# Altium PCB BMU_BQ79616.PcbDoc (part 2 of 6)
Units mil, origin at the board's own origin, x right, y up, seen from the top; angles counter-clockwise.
Board outline 7605 x 4005 mil, 4 copper layers (Top Layer, Layer 1, Layer 2, Bottom Layer), stack 37.446 mil thick; 709 components, 447 nets, 2028 pads, 1862 vias.
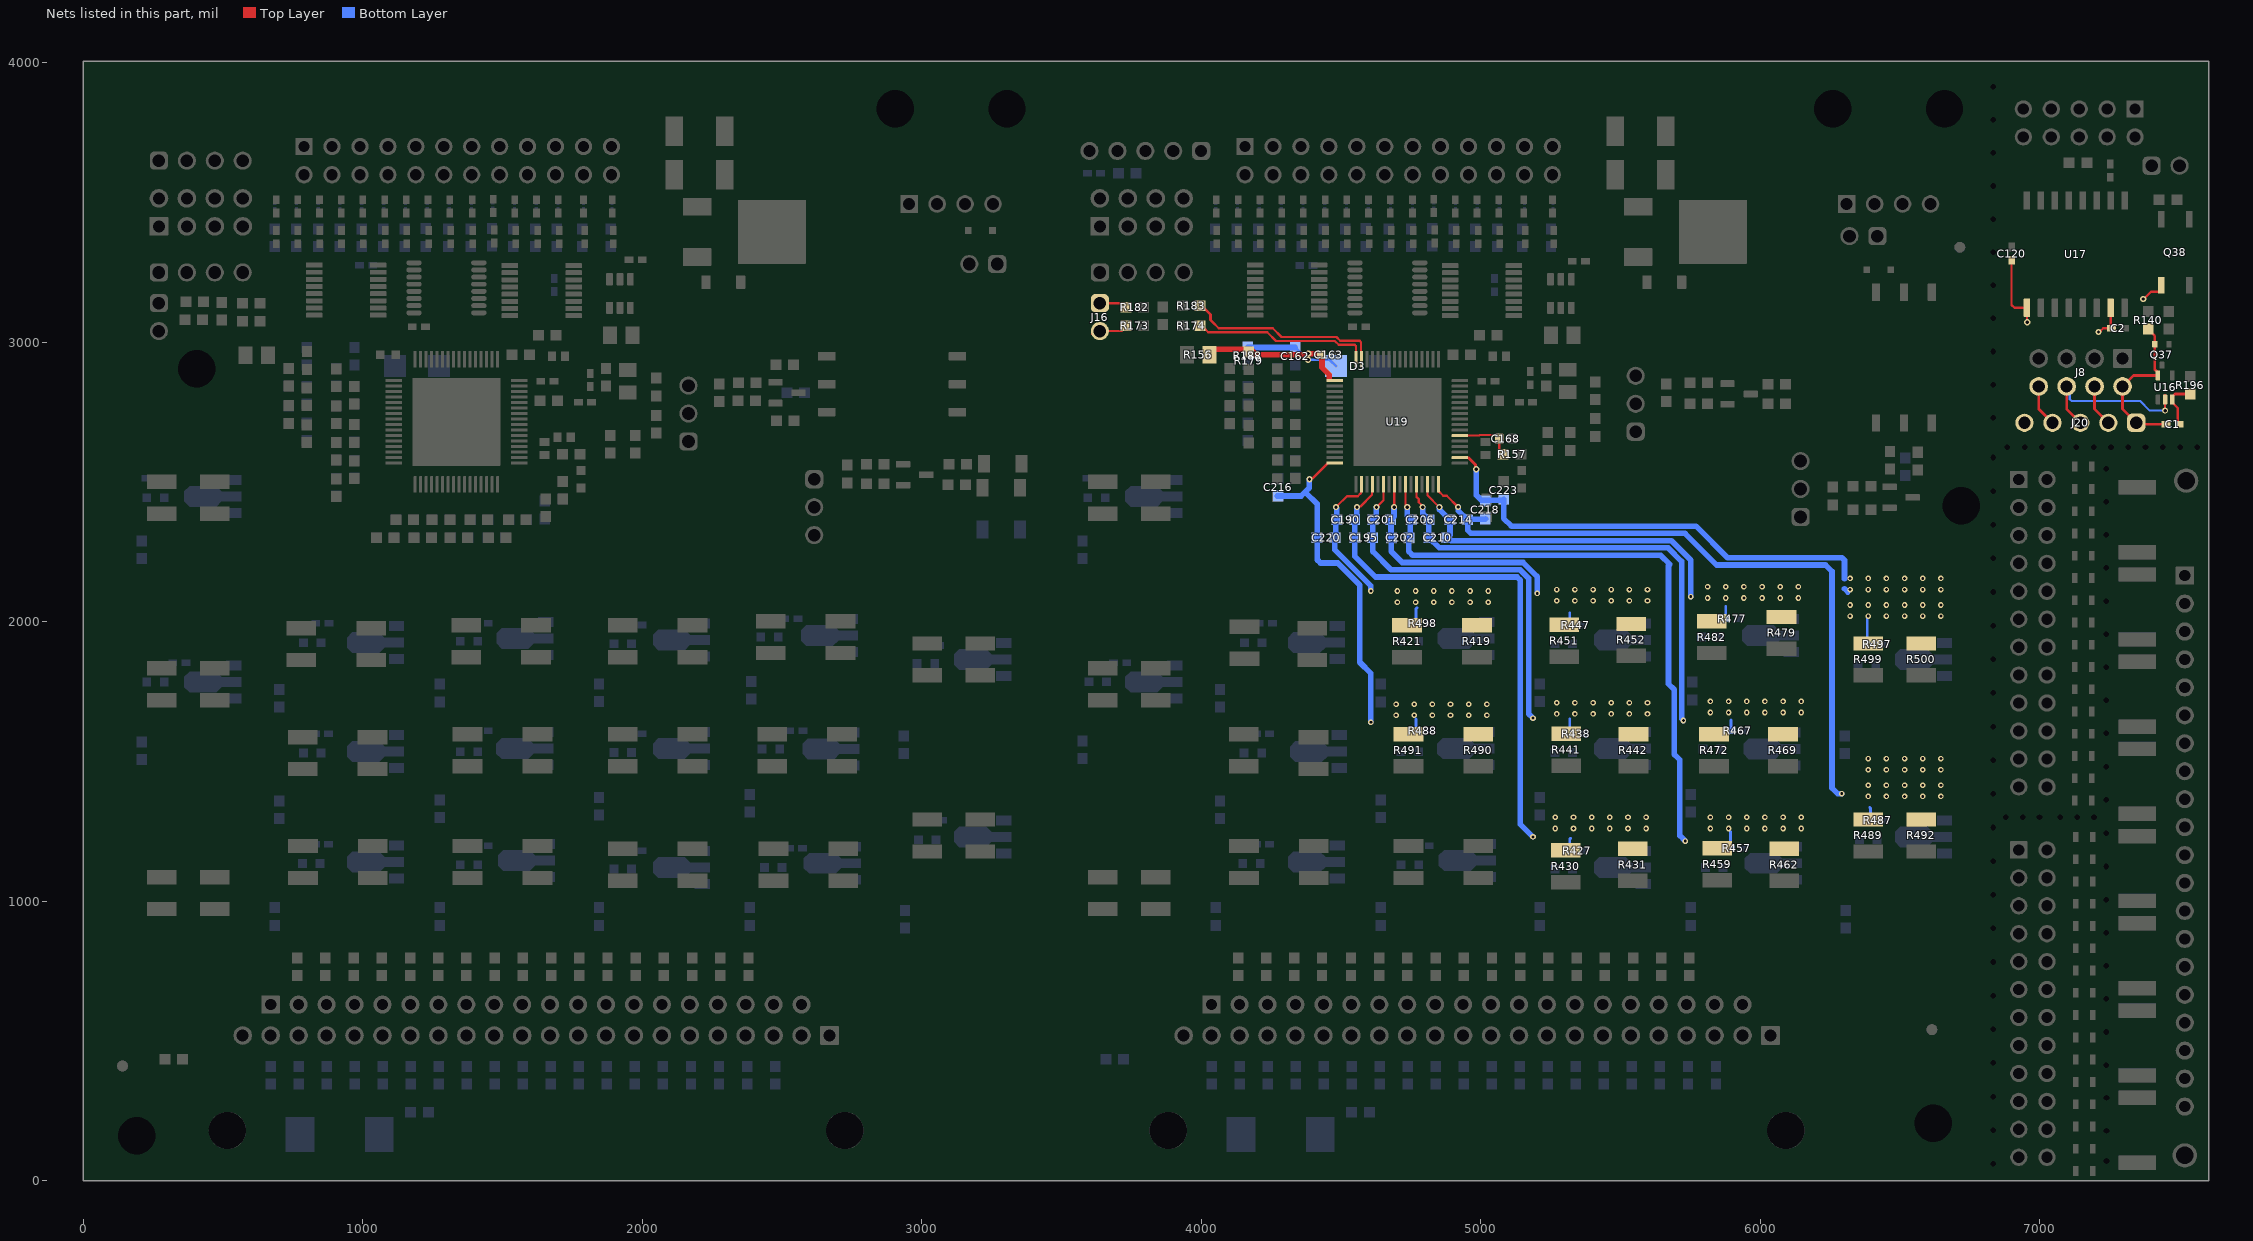
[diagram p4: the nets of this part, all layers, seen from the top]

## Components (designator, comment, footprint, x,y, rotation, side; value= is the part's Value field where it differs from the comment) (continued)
R432 "RC1210FR-0730RL" 1210 3647.36,1776.25 r90 top value=30.0
R433 "ERA-3AEB101V" 0603 5040.8,765 r90 top value=100
R434 "ERA-3AEB101V" 0603 4232.36,765 r90 top value=100
R435 "CRCW06031K00JNEA" 0603 5212.36,1340 r90 bottom value=1.0k
R436 "CRCW06031K00JNEA" 0603 3575.31,2257.26 r90 bottom value=1.0k
R437 "CRCW0402300RJNED" 0402 3615.31,2513.75 r0 bottom value=300
R438 "CRCW0402300RJNED" 0402 5342.36,1598.77 r0 bottom value=300
R439 "RC1210FR-0730RL" 1210 3647.36,2443.75 r90 top value=30.0
R440 "RC1210FR-0730RL" 1210 3837.36,2443.75 r90 top value=30.0
R441 "RC1210FR-0730RL" 1210 5306.93,1542.09 r90 top value=30.0
R442 "RC1210FR-0730RL" 1210 5546.93,1540 r90 top value=30.0
R443 "ERA-3AEB101V" 0603 5141.74,765 r90 top value=100
R444 "ERA-3AEB101V" 0603 4332.36,765 r90 top value=100
R445 "CRCW06031K00JNEA" 0603 5212.36,1746.5 r90 bottom value=1.0k
R446 "CRCW06031K00JNEA" 0603 4052.36,945 r90 bottom value=1.0k
R447 "CRCW0402300RJNED" 0402 5340.39,1988.15 r0 bottom value=300
R448 "CRCW0402300RJNED" 0402 4221.14,1203.76 r0 bottom value=300
R449 "RC1210FR-0730RL" 1210 4152.85,1140 r90 top value=30.0
R450 "RC1210FR-0730RL" 1210 4402.96,1140 r90 top value=30.0
R451 "RC1210FR-0730RL" 1210 5299.57,1932.09 r90 top value=30.0
R452 "RC1210FR-0730RL" 1210 5539.57,1935 r90 top value=30.0
R453 "ERA-3AEB101V" 0603 5242.67,765 r90 top value=100
R454 "ERA-3AEB101V" 0603 4432.36,765 r90 top value=100
R455 "CRCW06031K00JNEA" 0603 5752.36,945 r90 bottom value=1.0k
R456 "CRCW06031K00JNEA" 0603 4067.36,1326.5 r90 bottom value=1.0k
R457 "CRCW0402300RJNED" 0402 5917.36,1190 r0 bottom value=300
R458 "CRCW0402300RJNED" 0402 4221.14,1598.76 r0 bottom value=300
R459 "RC1210FR-0730RL" 1210 5846.93,1132.09 r90 top value=30.0
R460 "RC1210FR-0730RL" 1210 4151.82,1539.84 r90 top value=30.0
R461 "RC1210FR-0730RL" 1210 4401.93,1530 r90 top value=30.0
R462 "RC1210FR-0730RL" 1210 6086.93,1130 r90 top value=30.0
R463 "ERA-3AEB101V" 0603 5343.61,765 r90 top value=100
R464 "ERA-3AEB101V" 0603 4536.11,765 r90 top value=100
R465 "CRCW06031K00JNEA" 0603 5752.36,1350 r90 bottom value=1.0k
R466 "CRCW06031K00JNEA" 0603 4067.36,1726.5 r90 bottom value=1.0k
R467 "CRCW0402300RJNED" 0402 5920,1610 r0 bottom value=300
R468 "CRCW0402300RJNED" 0402 4231.38,1995 r0 bottom value=300
R469 "RC1210FR-0730RL" 1210 6081.93,1540 r90 top value=30.0
R470 "RC1210FR-0730RL" 1210 4155,1925 r90 top value=30.0
R471 "RC1210FR-0730RL" 1210 4396.93,1920 r90 top value=30.0
R472 "RC1210FR-0730RL" 1210 5835.43,1540 r90 top value=30.0
R473 "ERA-3AEB101V" 0603 5444.55,765 r90 top value=100
R474 "ERA-3AEB101V" 0603 4637.05,765 r90 top value=100
R475 "CRCW06031K00JNEA" 0603 5757.36,1752.05 r90 bottom value=1.0k
R476 "CRCW06031K00JNEA" 0603 4642.36,945 r90 bottom value=1.0k
R477 "CRCW0402300RJNED" 0402 5900.98,2010 r0 bottom value=300
R478 "CRCW0402300RJNED" 0402 4792.36,1198.54 r0 bottom value=300
R479 "RC1210FR-0730RL" 1210 6076.93,1960 r90 top value=30.0
R480 "RC1210FR-0730RL" 1210 4741.82,1140 r90 top value=30.0
R481 "RC1210FR-0730RL" 1210 4991.93,1140 r90 top value=30.0
R482 "RC1210FR-0730RL" 1210 5826.82,1945 r90 top value=30.0
R483 "ERA-3AEB101V" 0603 5545.49,765 r90 top value=100
R484 "ERA-3AEB101V" 0603 4737.99,765 r90 top value=100
R485 "CRCW06031K00JNEA" 0603 6307.36,935 r90 bottom value=1.0k
R486 "CRCW06031K00JNEA" 0603 4642.36,1330 r90 bottom value=1.0k
R487 "CRCW0402300RJNED" 0402 6420.71,1290 r0 bottom value=300
R488 "CRCW0402300RJNED" 0402 4792.36,1610 r0 bottom value=300
R489 "RC1210FR-0730RL" 1210 6387.36,1235 r90 top value=30.0
R490 "RC1210FR-0730RL" 1210 4991.93,1540 r90 top value=30.0
R491 "RC1210FR-0730RL" 1210 4741.82,1540 r90 top value=30.0
R492 "RC1210FR-0730RL" 1210 6576.93,1235 r90 top value=30.0
R493 "ERA-3AEB101V" 0603 5646.42,765 r90 top value=100
R494 "ERA-3AEB101V" 0603 4838.92,765 r90 top value=100
R495 "CRCW06031K00JNEA" 0603 6302.36,1560 r90 bottom value=1.0k
R496 "CRCW06031K00JNEA" 0603 4642.36,1745 r90 bottom value=1.0k
R497 "CRCW0402300RJNED" 0402 6420,1920 r0 bottom value=300
R498 "CRCW0402300RJNED" 0402 4792.36,1995 r0 bottom value=300
R499 "RC1210FR-0730RL" 1210 6387.36,1865 r90 top value=30.0
R500 "RC1210FR-0730RL" 1210 6576.93,1865 r90 top value=30.0
R501 "ERA-3AEB101V" 0603 5747.36,765 r90 top value=100
RT1 "ERT-J1VG103GA" 0603S 7156.81,2555 r0 top value=10k
RT2 "ERT-J1VG103GA" 0603S 7156.81,2475.33 r180 top value=10k
RT3 "ERT-J1VG103GA" 0603S 7156.81,2395.67 r0 top value=10k
RT4 "ERT-J1VG103GA" 0603S 7156.81,2316 r180 top value=10k
RT5 "ERT-J1VG103GA" 0603S 7156.81,2236.33 r0 top value=10k
RT6 "ERT-J1VG103GA" 0603S 7156.81,2156.67 r180 top value=10k
RT7 "ERT-J1VG103GA" 0603S 7156.81,2077 r0 top value=10k
RT8 "ERT-J1VG103GA" 0603S 7156.81,1997.33 r180 top value=10k
RT9 "ERT-J1VG103GA" 0603S 7156.81,1917.67 r0 top value=10k
RT10 "ERT-J1VG103GA" 0603S 7156.81,1838 r180 top value=10k
RT11 "ERT-J1VG103GA" 0603S 7156.81,1758.33 r0 top value=10k
RT12 "ERT-J1VG103GA" 0603S 7156.81,1678.67 r180 top value=10k
RT13 "ERT-J1VG103GA" 0603S 7156.81,1599 r0 top value=10k
RT14 "ERT-J1VG103GA" 0603S 7156.81,1519.33 r180 top value=10k
RT15 "ERT-J1VG103GA" 0603S 7156.81,1439.67 r0 top value=10k
RT16 "ERT-J1VG103GA" 0603S 7156.81,1360 r180 top value=10k
RT17 "ERT-J1VG103GA" 0603S 7160,1229.53 r0 top value=10k
RT18 "ERT-J1VG103GA" 0603S 7160,1149.87 r180 top value=10k
RT19 "ERT-J1VG103GA" 0603S 7160,1070.2 r0 top value=10k
RT20 "ERT-J1VG103GA" 0603S 7160,990.53 r180 top value=10k
RT21 "ERT-J1VG103GA" 0603S 7160,910.87 r0 top value=10k
RT22 "ERT-J1VG103GA" 0603S 7160,831.2 r180 top value=10k
RT23 "ERT-J1VG103GA" 0603S 7160,751.53 r0 top value=10k
RT24 "ERT-J1VG103GA" 0603S 7160,671.87 r180 top value=10k
RT25 "ERT-J1VG103GA" 0603S 7160,592.2 r0 top value=10k
RT26 "ERT-J1VG103GA" 0603S 7160,512.53 r180 top value=10k
RT27 "ERT-J1VG103GA" 0603S 7160,432.87 r0 top value=10k
RT28 "ERT-J1VG103GA" 0603S 7160,353.2 r180 top value=10k
RT29 "ERT-J1VG103GA" 0603S 7160,273.53 r0 top value=10k
RT30 "ERT-J1VG103GA" 0603S 7160,193.87 r180 top value=10k
RT31 "ERT-J1VG103GA" 0603S 7160,114.2 r0 top value=10k
RT32 "ERT-J1VG103GA" 0603S 7160,34.53 r180 top value=10k
T1 "HMU1228NL" FP-HMU1228NL_SMT_TRANSFORMER_8MM89_10MM09-MFG 6515,2945 r90 top
T2 "HMU1228NL" FP-HMU1228NL_SMT_TRANSFORMER_8MM89_10MM09-MFG 2893.76,2850 r180 top
TP1 "A1M_CELL16S" Keystone5010 7525,2505 r0 top
TP2 "A1M_CELL0S" Keystone5011 7520,90 r0 top
U1 "ESD2CAN24DBZR" DBZ0003A-MFG 5925,2815 r0 top
U2 "ESD2CAN24DBZR" DBZ0003A-MFG 2517.91,2820 r0 top
U3 "TPS22810TDBVRQ1" FP-DBV0006A-MFG 1920,3174.55 r90 top
U4 "BQ79616PAPQ1" PAP0064F-MFG 1334.41,2715.59 r0 top
U5 "TMUX1574PWR" PW0016A_N 1299,3195 r180 top
U7 "TMUX1308PWR" PW0016A-MFG 940.17,3186.61 r0 top
U8 "TMUX1308PWR" PW0016A-MFG 1640,3185 r0 top
U9 "ESD2CAN24DBZR" DBZ0003A-MFG 6505,2445 r0 top
U15 "ESD2CAN24DBZR" DBZ0003A-MFG 2974.69,2526.3 r0 top
U16 "TMUX1102DCKR" DCK0005A-MFG 7449.41,2838.31 r90 top
U17 "ISO7742DWR" DW0016B_HV 7129.95,3315.5 r270 top
U18 "TPS22810TDBVRQ1" FP-DBV0006A-MFG 5287.36,3174.55 r90 top
U19 "BQ79616PAPQ1" PAP0064F-MFG 4701.77,2715.59 r0 top
U20 "TMUX1574PWR" PW0016A_N 4666.36,3195 r180 top
U22 "TMUX1308PWR" PW0016A-MFG 4307.54,3186.61 r0 top
U23 "TMUX1308PWR" PW0016A-MFG 5005,3185 r0 top

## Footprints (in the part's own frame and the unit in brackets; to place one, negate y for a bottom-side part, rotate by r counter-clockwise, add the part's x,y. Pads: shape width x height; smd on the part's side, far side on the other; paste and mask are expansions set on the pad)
0402 [mm] "0402 from SM-752 data"
  rect 0.8x0.6 smd: 1(-0.6,0) 2(0.6,0)
  silkscreen extent -1.22,-0.52 1.22,0.52, body extent -0.55,-0.3 0.55,0.3, height 0.6
0603 [mm] "0603 from SM-752 data"
  rect 1x0.95 smd: 1(-0.8,0) 2(0.8,0)
  silkscreen extent -1.52,-0.69 1.52,0.69, body extent -0.87,-0.47 0.87,0.47, height 1
0603_HV [mil] "Ernesto recommended land pattern.  26 mil between pads."
  rect 30x30 smd: 1(-28,0) 2(28,0)
  silkscreen extent -52,-24 52,24, body extent -34,-19 34,19, height 39
0603S [mil]
  rect 20x35 smd: 1(-30,0) 2(30,0)
  body extent -34,-19 34,19, height 39
0805_HV [mil] "0805 with 30mil clearance between pads"
  rect 50x63 smd: 1(-40,0) 2(40,0)
  silkscreen extent -74,-40 74,40, body extent -43,-29 43,29, height 57
1206_180 [mm] "1206_180"
  rect 1.1x1.6 smd: 1(-1.7,0) 2(1.7,0)
  silkscreen extent -0.9,-1 0.9,1, body extent -1.75,-0.95 1.75,0.95, height 1.8
1210 [mm] "1210 from SM-752 data"
  rect 1.3x2.7 smd: 1(-1.45,0) 2(1.45,0)
  silkscreen extent -2.32,-1.57 2.32,1.57, body extent -1.7,-1.35 1.7,1.35, height 1.35
2010 [mm] "Chip Capacitor, Body 5.08x2.54mm, IPC Medium Density"
  rect 1.6x2.7 smd: 1(-2.3,0) 2(2.3,0)
  silkscreen extent -3.42,-1.65 3.42,1.65, body extent -2.73,-1.45 2.73,1.45, height 1.66
2512 [mm] "Chip Resistor, Body 6.3x3.2mm, IPC Medium Density"
  rect 1.3x3.4 smd: 1(-2.95,0) 2(2.95,0)
  silkscreen extent -1.9,-1.6 1.9,1.6, body extent -3.22,-1.67 3.22,1.67, height 0.71
CE_Mark_5mm [mil] "Minimum text height for CE Mark"
  silkscreen extent -138,-98 138,98
DBZ0003A-MFG [mm]
  rrect17% 1.3x0.6 smd paste+0 mask+0: 1(-1.05,0.95) 2(-1.05,-0.95) 3(1.05,0)
  silkscreen extent -0.7,-1.52 0.7,1.52, body extent -1.18,-1.46 1.19,1.46, height 1.12
DCK0005A-MFG [mm]
  rrect25% 0.9x0.4 smd paste-1000 mask+0: 1(-1.1,0.65) 2(-1.1,0) 3(-1.1,-0.65) 4(1.1,-0.65) 5(1.1,0.65)
  silkscreen extent -2.22,-1.07 0.27,1.07, body extent -1.65,-1.33 1.65,1.33, height 0.25
DFG0004A-MFG [mm]
  rrect17% 1.5x0.6 smd paste+0 mask+0: 1(-3,1.27) 2(-3,-1.27) 3(3,-1.27) 4(3,1.27)
  silkscreen extent -4.42,-1.81 1.85,1.81, body extent -3.85,-2.05 3.85,2.05, height 0.25
DPAK [mm] "D-PAK, 3-Pads, Body 6.22x6.73mm (max), TO-252AA using nominal STEP model"
  rrect6% 2.6x1.6 smd: 1(-3.4,2.28) 3(-3.4,-2.28)
  rrect2% 6.2x5.8 smd paste-3: 2(3.4,0)
  body extent -3.86,-3.29 5.84,3.29, height 2.48
DW0016B_HV [mm] "SOIC-16, HV/isolation option"
  rrect17% 1.65x0.6 smd: 1(-4.875,4.445) 2(-4.875,3.175) 3(-4.875,1.905) 4(-4.875,0.635) 5(-4.875,-0.635) 6(-4.875,-1.905) 7(-4.875,-3.175) 8(-4.875,-4.445) 9(4.875,-4.445) 10(4.875,-3.175) 11(4.875,-1.905) 12(4.875,-0.635) 13(4.875,0.635) 14(4.875,1.905) 15(4.875,3.175) 16(4.875,4.445)
  body extent -5.17,-5.15 5.17,5.15, height 2.59
FCC_disclaimer [mil]
Fiducial10-30 [mm]
  round 1 smd mask+1: 1(0,0)
  Top Layer keep-out circle w1.678: c0,0 r0.75
FP-705550056_HDR22-MFG [mm]
  rrect6% 1.69x1.69 hole 1.09 paste-1000 mask+0: 1(26.67,6.145)
  round 1.69 hole 1.09 paste-1000 mask+0: 2(24.13,6.145) 3(21.59,6.145) 4(19.05,6.145) 5(16.51,6.145) 6(13.97,6.145) 7(11.43,6.145) 8(8.89,6.145) 9(6.35,6.145) 10(3.81,6.145) 11(1.27,6.145) 12(-1.27,6.145) 13(-3.81,6.145) 14(-6.35,6.145) 15(-8.89,6.145) 16(-11.43,6.145) 17(-13.97,6.145) 18(-16.51,6.145) 19(-19.05,6.145) 20(-21.59,6.145) 21(-24.13,6.145) 22(-26.67,6.145)
  round 3.4 hole 3.4 unplated paste-1000 mask+0: ""(-28.07,-2.495) ""(28.07,-2.495)
  body extent -30.18,-7.04 30.18,7.09, height 0.25
FP-61300821121_HDR8-MFG [mm]
  rrect6% 1.7x1.7 hole 1.1 paste-1000 mask+0: 1(-3.81,-1.27)
  round 1.7 hole 1.1 paste-1000 mask+0: 2(-3.81,1.27) 3(-1.27,-1.27) 4(-1.27,1.27) 5(1.27,-1.27) 6(1.27,1.27) 7(3.81,-1.27) 8(3.81,1.27)
  body extent -5.33,-2.72 5.33,2.72, height 0.25
"FP-C0603C105K8RACAUTO_0603 (1608 Metric)-MFG" [mm]
  rrect13% 0.75x0.9 smd paste+0 mask+0: 1(-0.6,0) 2(0.6,0)
  body extent -1.2,-0.6 1.2,0.6, height 0.25
FP-DBV0006A-MFG [mm]
  rrect17% 1.1x0.6 smd paste+0 mask+0: 1(-1.3,0.95) 2(-1.3,0) 3(-1.3,-0.95) 4(1.3,-0.95) 5(1.3,0) 6(1.3,0.95)
  silkscreen extent -2.52,-1.53 0.35,1.53, body extent -1.4,-1.45 1.4,1.45, height 1.45
FP-GCM31MR72A224KA37L_1206-MFG [mm]
  rrect12% 0.85x1.2 smd paste+0 mask+0: 1(-1.575,0) 2(1.575,0)
  body extent -2.1,-0.97 2.1,0.97, height 0.25
FP-HMU1228NL_SMT_TRANSFORMER_8MM89_10MM09-MFG [mm]
  rrect13% 1.585x0.76 smd paste+0 mask+0: 1(-5.937,2.54) 2(-5.937,0) 3(-5.937,-2.54) 4(5.937,-2.54) 5(5.937,0) 6(5.937,2.54)
  silkscreen extent -7.5,-4.51 5.08,4.51, body extent -6.83,-4.61 6.83,4.61, height 0.25
FP-SSQ-112-04-G-D_CONN_RCPT24-MFG [mm]
  rrect6% 1.57x1.57 hole 1.02 paste-1000 mask+0: 1(-13.97,1.28)
  round 1.57 hole 1.02 paste-1000 mask+0: 2(-13.97,-1.28) 3(-11.43,1.28) 4(-11.43,-1.28) 5(-8.89,1.28) 6(-8.89,-1.28) 7(-6.35,1.28) 8(-6.35,-1.28) 9(-3.81,1.28) 10(-3.81,-1.28) 11(-1.27,1.28) 12(-1.27,-1.28) 13(1.27,1.28) 14(1.27,-1.28) 15(3.81,1.28) 16(3.81,-1.28) 17(6.35,1.28) 18(6.35,-1.28) 19(8.89,1.28) 20(8.89,-1.28) 21(11.43,1.28) 22(11.43,-1.28) 23(13.97,1.28) 24(13.97,-1.28)
  silkscreen extent -16.34,-2.54 15.62,2.54, body extent -15.49,-2.48 15.49,2.48, height 8.65
FP-TSW-105-08-L-D-RA_HDR10-MFG [mm]
  rrect6% 1.57x1.57 hole 1.02 paste-1000 mask+0: 1(-5.08,2.79)
  round 1.57 hole 1.02 paste-1000 mask+0: 2(-5.08,5.33) 3(-2.54,2.79) 4(-2.54,5.33) 5(0,2.79) 6(0,5.33) 7(2.54,2.79) 8(2.54,5.33) 9(5.08,2.79) 10(5.08,5.33)
  body extent -6.64,-7.47 6.64,6.21, height 0.25
IEC_HighVoltage_Small [mil]
  silkscreen extent -107,-88 107,97
Keystone5010 [mil] "Keystone Multipurpose loops"
  round 87 hole 63: 1(0,0)
  silkscreen extent -70,-70 70,70, body extent -63,-63 63,62, height 319
Keystone5011 [mil] "Keystone Multipurpose loops"
  round 87 hole 63: 1(0,0)
  silkscreen extent -70,-70 70,70, body extent -63,-63 63,62, height 319
Label_650x200 [mil] "Thermal Transfer Label"
  round 1 on Mech13: 0(0,0)
  silkscreen extent -325,-100 325,100, body extent -325,-100 325,100, height 1
Molex_70551-0038 [mm] "Header(shrouded), 2.54mm, 4x1, R/A, TH"
  rect 1.6x1.6 hole 1.09: 1(0,3.81)
  round 1.6 hole 1.09: 2(0,1.27) 3(0,-1.27) 4(0,-3.81)
  round 0 hole 3.4 unplated paste+0 mask+0: MH1(8.64,-5.08) MH2(8.64,5.08)
  silkscreen extent 1.45,-6.98 12.88,7.32, body extent -0.71,-6.98 12.88,6.98, height 6.6
PAP0064F-MFG [mm]
  rrect33% 1.5x0.3 smd paste+0 mask+0: 1(-5.7,3.75) 2(-5.7,3.25) 3(-5.7,2.75) 4(-5.7,2.25) 5(-5.7,1.75) 6(-5.7,1.25) 7(-5.7,0.75) 8(-5.7,0.25) 9(-5.7,-0.25) 10(-5.7,-0.75) 11(-5.7,-1.25) 12(-5.7,-1.75) 13(-5.7,-2.25) 14(-5.7,-2.75) 15(-5.7,-3.25) 16(-5.7,-3.75) 33(5.7,-3.75) 34(5.7,-3.25) 35(5.7,-2.75) 36(5.7,-2.25) 37(5.7,-1.75) 38(5.7,-1.25) 39(5.7,-0.75) 40(5.7,-0.25) 41(5.7,0.25) 42(5.7,0.75) 43(5.7,1.25) 44(5.7,1.75) 45(5.7,2.25) 46(5.7,2.75) 47(5.7,3.25) 48(5.7,3.75)
  rrect33% 0.3x1.5 smd paste+0 mask+0: 17(-3.75,-5.7) 18(-3.25,-5.7) 19(-2.75,-5.7) 20(-2.25,-5.7) 21(-1.75,-5.7) 22(-1.25,-5.7) 23(-0.75,-5.7) 24(-0.25,-5.7) 25(0.25,-5.7) 26(0.75,-5.7) 27(1.25,-5.7) 28(1.75,-5.7) 29(2.25,-5.7) 30(2.75,-5.7) 31(3.25,-5.7) 32(3.75,-5.7) 49(3.75,5.7) 50(3.25,5.7) 51(2.75,5.7) 52(2.25,5.7) 53(1.75,5.7) 54(1.25,5.7) 55(0.75,5.7) 56(0.25,5.7) 57(-0.25,5.7) 58(-0.75,5.7) 59(-1.25,5.7) 60(-1.75,5.7) 61(-2.25,5.7) 62(-2.75,5.7) 63(-3.25,5.7) 64(-3.75,5.7)
  rrect1% 8x8 smd paste-1000 mask-1000: 65(0,0)
  silkscreen extent -5.82,-5.1 5.1,5.1, body extent -6.55,-6.55 6.55,6.55, height 0.25
Pb-Free_Overlay_Small [mil]
  silkscreen extent -46,-46 46,46
PW0016A-MFG [mm]
  rrect22% 1.5x0.45 smd paste+0 mask+0: 1(-2.9,2.275) 2(-2.9,1.625) 3(-2.9,0.975) 4(-2.9,0.325) 5(-2.9,-0.325) 6(-2.9,-0.975) 7(-2.9,-1.625) 8(-2.9,-2.275) 9(2.9,-2.275) 10(2.9,-1.625) 11(2.9,-0.975) 12(2.9,-0.325) 13(2.9,0.325) 14(2.9,0.975) 15(2.9,1.625) 16(2.9,2.275)
  silkscreen extent -4.32,-2.55 1.78,2.55, body extent -3.75,-2.8 3.75,2.8, height 0.25
PW0016A_N [mm] "TSOP, 16-Leads, Body 5x4.4mm, Pitch 0.65mm, IPC Medium Density"
  oval 1.4x0.45 smd: 1(-2.95,2.275) 2(-2.95,1.625) 3(-2.95,0.975) 4(-2.95,0.325) 5(-2.95,-0.325) 6(-2.95,-0.975) 7(-2.95,-1.625) 8(-2.95,-2.275) 9(2.95,-2.275) 10(2.95,-1.625) 11(2.95,-0.975) 12(2.95,-0.325) 13(2.95,0.325) 14(2.95,0.975) 15(2.95,1.625) 16(2.95,2.275)
  silkscreen extent -3.5,-2.55 1.85,2.75, body extent -3.21,-2.5 3.21,2.5, height 1
SMA [mm] "Molded Diode, 2-Leads, Body 4.3x2.6mm, IPC Medium Density, based on OnSemi component dimensions and land pattern"
  rect 2x2 smd: 1(-2,0) 2(2,0)
  silkscreen extent -3.66,-1.57 2.79,1.57, body extent -2.6,-1.3 2.6,1.3, height 2.42
SMC_265 [mm] "SMD, 2-Leads, Body 7.15x6.25mm"
  rect 2.6x3.2 smd: 1(-3.6,0) 2(3.6,0)
  silkscreen extent -5.6,-3.23 5.3,3.22, body extent -4.08,-3.13 4.08,3.13, height 2.65
SOD-323-Bi [mm] "SOD323, 2-Leads, Body 1.9x1.45mm, No Polarity Mark"
  rect 0.6x0.6 smd paste-0.05: 1(-1.1,0) 2(1.1,0)
  silkscreen extent -1.53,-0.77 1.53,0.77, body extent -1.27,-0.65 1.27,0.65, height 1.02
SOT-89-3 [mm] "SOT, 3-Leads, Body 4.6 x 2.6 mm, Pitch 1.5mm"
  rect 1.4x0.9 smd: 1(-1.9,1.5) 3(-1.9,-1.5)
  rect 1.8x0.9 smd: 2(-1.7,0)
  oct 3.4x1.9 smd: 4(0.9,0)
  silkscreen extent -1.3,-2.45 1.33,2.45, body extent -2.42,-2.28 1.83,2.32, height 1.62
SOT-323 [mm] "Diodes Inc recommended land pattern.  2016-02-24"
  rrect21% 0.6x0.47 smd: 1(-0.95,0.65) 2(-0.95,-0.65) 3(0.95,0)
  silkscreen extent -1.14,-1.22 0.77,1.22, body extent -1.13,-1.13 1.12,1.12, height 1.13
ST0201 [mm] "SMD, 2-Leads, Body 0.6x0.3mm"
  rect 0.425x0.3 smd paste-0.3: 1(-0.312,0) 2(0.312,0)
  silkscreen extent -1,-0.55 0.5,0.55, body extent -0.33,-0.18 0.33,0.18, height 0.33
TSW-120-07-G-S [mm] "Samtec 100mil, 1x20, 230 mil above insulator"
  rrect6% 1.65x1.65 hole 1.016: 1(-24.13,0)
  round 1.65 hole 1.016: 2(-21.59,0) 3(-19.05,0) 4(-16.51,0) 5(-13.97,0) 6(-11.43,0) 7(-8.89,0) 8(-6.35,0) 9(-3.81,0) 10(-1.27,0) 11(1.27,0) 12(3.81,0) 13(6.35,0) 14(8.89,0) 15(11.43,0) 16(13.97,0) 17(16.51,0) 18(19.05,0) 19(21.59,0) 20(24.13,0)
  silkscreen extent -25.4,-1.27 25.4,1.65, body extent -25.4,-1.27 25.4,1.27, height 8.38
WEEE_Minimum [mil] "WEEElie bin"
  silkscreen extent -95,-172 99,104
WL-SMCW_GREEN [mm] "WURTH"
  rect 0.8x0.8 smd: 1(-0.8,0) 2(0.8,0)
  silkscreen extent -1.9,-0.8 1.2,0.8, body extent -0.85,-0.45 0.85,0.45, height 0.8
WL-SMCW_RED [mm] "WURTH"
  rect 0.8x0.8 smd: 1(-0.8,0) 2(0.8,0)
  silkscreen extent -1.9,-0.8 1.2,0.8, body extent -0.85,-0.45 0.85,0.45, height 0.8
WURTH_61300211121 [mm] "Header, 2.54mm, 2x1, TH"
  rrect50% 1.65x1.65 hole 1.15: 1(-1.27,0)
  round 1.65 hole 1.15: 2(1.27,0)
  body extent -2.54,-1.27 2.54,1.27, height 8.54
WURTH_61300311121 [mm] "Header, 2.54mm, 3x1, TH"
  rrect50% 1.65x1.65 hole 1.15: 1(-2.54,0)
  round 1.65 hole 1.15: 2(0,0) 3(2.54,0)
  body extent -3.81,-1.27 3.81,1.27, height 8.54
WURTH_61300411121 [mm] "Header, 2.54mm, 4x1, TH"
  rrect50% 1.65x1.65 hole 1.15: 1(-3.81,0)
  round 1.65 hole 1.15: 2(-1.27,0) 3(1.27,0) 4(3.81,0)
  body extent -5.08,-1.27 5.08,1.27, height 8.54
Wurth_61300511121 [mm] "Header, 2.54mm, 5x1, TH"
  rrect50% 1.65x1.65 hole 1.1: 1(-5.08,0)
  round 1.65 hole 1.1: 2(-2.54,0) 3(0,0) 4(2.54,0) 5(5.08,0)
  body extent -6.35,-1.27 6.35,1.27, height 8.54

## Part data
C1 C2 C4 C10 C11 C15 C39 C120 C159 C160 C170: library part CMP-0006350-2, "CAP, CERM, 0.1 uF, 10 V, +/- 10%, X7R, AEC-Q200 Grade 1, 0402", Cap_Case=0402, Manufacturer=MuRata, Supplier Part Number 1=81-GCM155R71A104K5D, TempCo=X7R, Tolerance_%=10%, Value1=Unknown, Value2=10V, ValueDisplayed=0.1uF
C3 C154: library part CMP-0087125-1, "Multilayer Ceramic Capacitors MLCC - SMD/SMT 1206 0.22uF 100volts X7R +/-10%", Manufacturer=Murata, TempCo=15%, Tolerance_%=10%
C5 C6 C7 C54 C55 C58 C59 C62 C63 C66 C67 C70 C71 C74 C75 C78 C79 C190 C191 C194 C195 C199 C201 C202 C204 C206 C208 C210 C212 C214 C216 C218 C220 C223: library part CMP-0007138-4, "CAP, CERM, 0.47 uF, 16 V, +/- 10%, X7R, AEC-Q200 Grade 1, 0603", Cap_Case=0603, Manufacturer=MuRata, Supplier Part Number 1=490-4775-1-ND, TempCo=X7R, Tolerance_%=10%, Value1=Unknown, Value2=16V
C8 C155: library part CMP-0008323-2, "CAP, CERM, 1 uF, 16 V, +/- 10%, X7R, 0805", Cap_Case=0805, Manufacturer=MuRata, Supplier Part Number 1=490-1691-1-ND, TempCo=X7R, Tolerance_%=10%, Value1="0.003 ohm", Value2=16V, ValueDisplayed=1uF
C9 C16 C19 C158 C165 C168: library part CMP-0087157-1, "CAP CER 0603 1UF 10V X7R 10%", Manufacturer=KEMET, TempCo=15%, Tolerance_%=10%
C12 C20 C21 C22 C23 C24 C25 C26 C27 C28 C29 C31 C32 C33 C34 C35 C36 C37 C38 C161 C171 C172 C173 C174 C175 C176 C177 C178 C180 C181 C182 C183 C184 C185 C186 C187 C188 C189: library part CMP-0006356-2, "CAP, CERM, 0.1 uF, 50 V, +/- 10%, X7R, AEC-Q200 Grade 1, 0402", Cap_Case=0402, Manufacturer=MuRata, Supplier Part Number 1=490-10672-1-ND, TempCo=X7R, Tolerance_%=10%, Value1=Unknown, Value2=50V, ValueDisplayed=0.1uF
C13 C30 C52 C53 C56 C57 C60 C61 C64 C65 C68 C69 C72 C73 C76 C77 C80 C81 C84 C162 C179 C192 C193 C196 C197 C198 C200 C203 C205 C207 C209 C211 C213 C215 C217 C219 C221 C222: library part CMP-0007138-4, "CAP, CERM, 0.47 uF, 16 V, +/- 10%, X7R, AEC-Q200 Grade 1, 0603", Cap_Case=0603, Manufacturer=MuRata, Supplier Part Number 1=490-4775-1-ND, TempCo=X7R, Tolerance_%=10%, Value1=Unknown, Value2=16V, ValueDisplayed=0.47uF
C14 C163: library part CMP-0084773-1, "CAP, CERM, 0.01 µF, 100 V,+/- 10%, X7R, AEC-Q200 Grade 1, 0603", Cap_Case=0603, Manufacturer=MuRata, TempCo=X7R, Tolerance_%=10%, Value2=100V, ValueDisplayed=0.01µF
C17 C166: library part CMP-0007865-2, "CAP, CERM, 4.7 uF, 10 V, +/- 20%, X7R, 0805", Cap_Case=0805, Manufacturer=TDK, Supplier Part Number 1=445-1605-1-ND, TempCo=X7R, Tolerance_%=20%, Value1=Unknown, Value2=10V, ValueDisplayed=4.7uF
C18 C167: library part CMP-0006906-5, "CAP, CERM, 2.2 uF, 10 V, +/- 10%, X5R, 0603", Cap_Case=0603, Manufacturer=Kemet, Supplier Part Number 1=399-4911-1-ND, TempCo=X5R, Tolerance_%=10%, Value1=Unknown, Value2=10V, ValueDisplayed=2.2uF
C40 C41 C153: library part CMP-0077201-1, "CAP, CERM, 2200 pF, 2000 V,+/- 10%, X7R, AEC-Q200 Grade 1, 1206", Cap_Case=1206, Manufacturer="Knowles Capacitors", Supplier Part Number 1=1206J2K00222KXR-ND, TempCo=X7R, Tolerance_%=10%, Value2=2000V, ValueDisplayed=2200pF
C42 C43 C44 C45 C48 C49 C50 C51: library part CMP-0860329-1, "CAP, CERM, 220 pF, 50 V,+/- 5%, X7R, 0603", Cap_Case=0603, Manufacturer="Samsung Electro-Mechanics", TempCo=X7R, Tolerance_%=5%, Value2=50V, ValueDisplayed=220pF
C46 C47: library part CMP-0750041-1, "CAP, CERM, 100 pF, 50 V,+/- 5%, C0G/NP0, AEC-Q200 Grade 1, 0603", Cap_Case=0603, Manufacturer=MuRata, TempCo=C0G/NP0, Tolerance_%=5%, Value2=50V, ValueDisplayed=100pF
C82 C83 C85 C86 C88 C89 C90 C91 C92 C93 C94 C95 C96 C97 C98 C99 C100 C101 C102 C103 C104 C105 C106 C107 C108 C109 C110 C111 C112 C113 C114 C115 C116 C117 C118 C119 C121 C122: library part CMP-0079993-1, "CAP, CERM, 0.01 µF, 100 V,+/- 10%, X7R, 0603", Cap_Case=0603, Manufacturer="Wurth Elektronik", Supplier Part Number 1=45AC8565, TempCo=X7R, Tolerance_%=10%, Value2=100V, ValueDisplayed=0.01µF
C152 C169: library part CMP-0007086-4, "CAP, CERM, 0.022 uF, 100 V, +/- 10%, X7R, AEC-Q200 Grade 1, 0603", Cap_Case=0603, Manufacturer=TDK, Supplier Part Number 1=445-5814-1-ND, TempCo=X7R, Tolerance_%=10%, Value1="0.083542 ohm", Value2=100V, ValueDisplayed=0.022uF
D1 D45: library part CMP-0002894-2, "LED, Green, SMD", Color=green, Manufacturer="Wurth Elektronik", Value1=W, Value2=2V
D2 D3: library part CMP-0084973-1, "Diode, TVS, Uni, 70 V, 113 Vc, 400 W, 3.5 A, SMA", Manufacturer="WÜRTH ELEKTRONIK", PartNumber=824500701, Value1=113V
D4 D5 D10 D11 D16 D17 D22 D23 D28 D29 D34 D35 D41 D42 D47 D48 D57 D58 D59 D60 D61 D62 D63 D64 D65 D66 D67 D68 D69 D70 D71 D72: library part CMP-0002947-3, "LED, Red, SMD", Color=Red, Manufacturer="Wurth Elektronik", Power_TotalModule=72mW, Value1=0.072W, Value2=2V
D6 D7 D12 D13 D14 D15 D18 D19 D20 D21 D24 D25 D26 D27 D30 D31 D32 D33 D36 D37 D38 D39 D40 D43 D46 D49 D50 D51 D52 D53 D54 D55: library part CMP-0006069-3, "Diode, TVS, Uni, 6.1 V, 0201", Manufacturer=TI, PartNumber=ESD441, Value1=20W
D8 D9: library part CMP-0065114-2, "Diode, TVS, Bi, 8 V, 18.5 Vc, SOD-323", Manufacturer=TI, PartNumber=TSD05CDYFR, Value1=400W
D44 D56: library part CMP-0005734-3, "Diode, TVS, Uni, 70 V, 113 Vc, SMC", Manufacturer="Würth Elektronik", PartNumber=824540701, Value1=1500W
FID1 FID2 FID3 FID4 FID5 FID6: library part CMP-0077181-1, "Fiducial mark.  There is nothing to buy or mount.", Manufacturer=N/A
J1 J17 J19: library part CMP-0054798-2, "Header, 2.54 mm, 4x1, Gold, TH", Color=Black, Manufacturer="Wurth Elektronik", Supplier Part Number 1=732-5317-ND
J2 J7 J9 J11: library part CMP-0096812-1, "24 Position Receptacle Connector 0.100\" (2.54mm) Through Hole Gold", Digikey Part Number=SAM11919-ND, Manufacturer="Wurth Elektronik", Mouser Part Number=200-SSQ11204GD, Operating Temperature Range="-55°C to +125°C", Part Number=61302421121, Voltage_V=655V
J3 J5 J16 J32 J33: library part CMP-0054794-2, "Header, 2.54 mm, 2x1, Gold, TH", Color=Black, Manufacturer="Wurth Elektronik", Supplier Part Number 1=732-5315-ND
J4 J18: library part CMP-0075434-1, "Header, 100mil, 20x1, Gold, TH", Color=Black, Current_A=6.3A, Manufacturer="Wurth Elektronik", PartNumber=61302011121, Supplier Part Number 1=SAM1029-20-ND, Voltage_V=550V
J6 J8 J14: library part CMP-0087153-1, "CONN HEADER VERT 8POS 2.54MM", Current_A=3A, Manufacturer="Wurth Electronics", Voltage_V=250V
J10 J21: library part CMP-0087165-1, "Connector Header Through Hole, Right Angle 22 position 0.100\" (2.54mm)", Current_A=3A, Manufacturer=Molex, Voltage_V=250V
J12: library part CMP-0086439-1, "CONN HEADER 10POS .100 DL R/A AU", Current_A=6.3A, Manufacturer="Würth Elektronik", PartNumber=61301021021, Voltage_V=550V
J13 J20: library part CMP-0084909-1, "Header, 2.54mm, 5x1, Gold, TH", Color=Black, Current_A=3A, Manufacturer="Wurth Elektronik", Voltage_V=250V
J15: library part CMP-0075434-1, "Header, 100mil, 20x1, Gold, TH", Color=Black, Current_A=6.3A, Manufacturer="Wurth Elektronik", Supplier Part Number 1=SAM1029-20-ND, Voltage_V=550V
J26 J27 J28 J29: library part CMP-0054796-4, "Header, 2.54 mm, 3x1, Gold, TH", Manufacturer="Wurth Elektronik", Supplier Part Number 1=732-5316-ND
J30 J31: library part CMP-0055239-1, "Header(shrouded), 2.54mm, 4x1, R/A, Gold, TH", Color=Black, Current_A=3A, Manufacturer=Molex, Supplier Part Number 1=0705510038-ND, Voltage_V=250V
LBL1: library part CMP-0003625-1, "Thermal Transfer Printable Labels, 0.650\" W x 0.200\" H - 10,000 per roll", Manufacturer=Brady, Supplier Part Number 1=97C5133
Logo1: library part CMP-0074844-1
LOGO2: library part CMP-0074839-1
Logo3: library part CMP-0074847-1, "FCC_disclaimer"
Logo4: library part CMP-0074835-1, "IEC 61010-1 High Voltage Warning"
Logo5: library part CMP-0074769-1
Q1 Q39: library part CMP-0000504-4, "Transistor, NPN, 150 V, 1 A, AEC-Q101, DPAK", Manufacturer="Diodes Inc.", PartNumber=ZXTN4004KTC, Value1="1 A"
Q2 Q3 Q4 Q5 Q6 Q7 Q8 Q9 Q10 Q11 Q12 Q13 Q14 Q15 Q16 Q17 Q40 Q41 Q42 Q43 Q44 Q45 Q46 Q47 Q48 Q49 Q50 Q51 Q52 Q53 Q54 Q55: library part CMP-0000384-2, "Transistor, NPN, 45 V, 1 A, SOT-89", Manufacturer="Diodes Inc.", Supplier Part Number 1=FCX690BCT-ND, Value1="1 A"
Q37: library part CMP-0000010-3, "MOSFET, P-CH, -20 V, -0.39 A, SOT-323", Alternate Manufacturer=None, Manufacturer="Infineon Technologies", Value1=1
Q38: library part CMP-0098363-1, "3.75-kVRMS, Single-Channel Opto-Emulator with Transistor Output", Emiiter Collector Voltage=7V, Forward Current=10mA, Manufacturer="Texas Instruments", Operating Temperature Range="to +150°C", Power_TotalModule=200mW, Voltage_Isolation_Vrms=3750Vrms
R1 R2 R3 R4 R5 R6 R7 R8 R10 R11 R14 R47 R51 R68 R70 R71 R76 R77 R79 R80 R83 R84 R87 R88 R91 R92 R150 R153 R154 R155 R174 R179 R183 R188 R408: library part CMP-0025885-5, "RES, 0, 5%, 0.1 W, 0603", Manufacturer=Yageo, Power_W=100mW, Supplier Part Number 1=311-0.0GRCT-ND, TempCo="200 ppm/C", Tolerance_%=5%, Value2=0.1W, Value_Code=0000, ValueDisplayed=0
R9 R192 R417 R418: library part CMP-0025697-4, "RES, 0, 5%, 0.1 W, AEC-Q200 Grade 0, 0603", Manufacturer=Vishay-Dale, Power_W=100mW, Supplier Part Number 1=541-0.0GCT-ND, TempCo="200 ppm/C", Tolerance_%=5%, Value2=0.1W, Value_Code=0000, ValueDisplayed=0
R12 R13 R16 R17 R20 R95 R106 R107 R123 R124 R134 R135 R136 R137 R138 R139 R427 R428 R437 R438 R447 R448 R457 R458 R467 R468 R477 R478 R487 R488 R497 R498: library part CMP-0026902-3, "RES, 300, 5%, 0.063 W, AEC-Q200 Grade 0, 0402", Manufacturer=Vishay-Dale, Power_W=63mW, Supplier Part Number 1=541-300JCT-ND, TempCo="200 ppm/C", Tolerance_%=5%, Value2=0.063W, Value_Code=300R, ValueDisplayed=300
R15 R18 R19 R21 R22 R23 R26 R27 R28 R67 R96 R99 R100 R101 R102 R103 R104 R105 R108 R109 R112 R113 R116 R117 R118 R119 R120 R121 R122 R125 R126 R127 R130 R131 R419 R420 R421 R422 R429 R430 R431 R432 R439 R440 R441 R442 R449 R450 R451 R452 R459 R460 R461 R462 R469 R470 R471 R472 R479 R480 R481 R482 R489 R490 R491 R492 R499 R500: library part CMP-0083073-1, "RES, 30.0, 1%, 0.5 W, 1210", Manufacturer=Yageo, Power_W=500mW, TempCo="100 ppm/C", Tolerance_%=1%, Value2=0.5W, Value_Code=30R0, ValueDisplayed=30.0
R24 R151: library part CMP-0016209-3, "RES, 100, 1%, 0.75 W, AEC-Q200 Grade 0, 2010", Manufacturer=Vishay-Dale, Power_W=750mW, Supplier Part Number 1=541-100ACCT-ND, TempCo="100 ppm/C", Tolerance_%=1%, Value2=0.75W, Value_Code=100R, ValueDisplayed=100
R25 R152: library part CMP-0016302-3, "RES, 200, 1%, 0.75 W, AEC-Q200 Grade 0, 2010", Manufacturer=Vishay-Dale, Power_W=750mW, Supplier Part Number 1=541-200ACCT-ND, TempCo="100 ppm/C", Tolerance_%=1%, Value2=0.75W, Value_Code=200R, ValueDisplayed=200
R29 R156: library part CMP-0020525-3, "RES, 30, 5%, 0.125 W, AEC-Q200 Grade 0, 0805", Manufacturer=Vishay-Dale, Power_W=125mW, Supplier Part Number 1=541-30ACT-ND, TempCo="200 ppm/C", Tolerance_%=5%, Value2=0.125W, Value_Code=30R0, ValueDisplayed=30
R30 R97 R98 R114 R115 R132 R133 R140 R142 R148 R149 R157 R164 R165 R180 R181 R197 R198 R213 R214 R425 R426 R435 R436 R445 R446 R455 R456 R465 R466 R475 R476 R485 R486 R495 R496: library part CMP-0025729-4, "RES, 1.0 k, 5%, 0.1 W, AEC-Q200 Grade 0, 0603", Manufacturer=Vishay-Dale, Power_W=100mW, Supplier Part Number 1=541-1.0KGCT-ND, TempCo="200 ppm/C", Tolerance_%=5%, Value2=0.1W, Value_Code=1k00, ValueDisplayed=1.0k
R31 R33 R35 R37 R39 R41 R43 R45 R49 R53 R55 R57 R59 R61 R63 R65 R158 R162 R166 R168 R170 R172 R178 R185 R187 R191 R196 R200 R202 R223 R411 R413 R415: library part CMP-0021998-4, "RES, 10.0 k, 1%, 0.1 W, AEC-Q200 Grade 0, 0603", Manufacturer=Vishay-Dale, Power_W=100mW, Supplier Part Number 1=541-10.0KHCT-ND, TempCo="100 ppm/C", Tolerance_%=1%, Value2=0.1W, Value_Code=10k0, ValueDisplayed=10.0k
R32 R34 R36 R38 R40 R42 R44 R48 R52 R54 R56 R58 R60 R62 R64 R66 R159 R163 R167 R169 R171 R175 R184 R186 R190 R199 R201 R220 R282 R412 R414 R416: library part CMP-0026852-3, "RES, 1.0 k, 5%, 0.063 W, AEC-Q200 Grade 0, 0402", Manufacturer=Vishay-Dale, Power_W=63mW, Supplier Part Number 1=541-1.0KJCT-ND, TempCo="200 ppm/C", Tolerance_%=5%, Value2=0.063W, Value_Code=1k00, ValueDisplayed=1.0k
R46 R50 R173 R182: library part CMP-0022409-5, "RES, 402, 1%, 0.1 W, AEC-Q200 Grade 0, 0603", Manufacturer=Vishay-Dale, Power_W=100mW, Supplier Part Number 1=541-402HCT-ND, TempCo="100 ppm/C", Tolerance_%=1%, Value2=0.1W, Value_Code=402R, ValueDisplayed=402
R69 R72 R75 R78 R81 R82 R89 R90: library part CMP-0025825-4, "RES, 51, 5%, 0.1 W, AEC-Q200 Grade 0, 0603", Manufacturer=Vishay-Dale, Power_W=100mW, Supplier Part Number 1=541-51GCT-ND, TempCo="200 ppm/C", Tolerance_%=5%, Value2=0.1W, Value_Code=51R0, ValueDisplayed=51
R73 R74 R85 R86: library part CMP-0022680-4, "RES, 1.00 k, 1%, 0.1 W, 0603", Manufacturer=Panasonic, Power_W=100mW, Supplier Part Number 1=P1.00KHCT-ND, TempCo="100 ppm/C", Tolerance_%=1%, Value2=0.1W, Value_Code=1k00, ValueDisplayed=1.00k
R93 R94 R110 R111 R128 R129 R144 R145 R160 R161 R176 R177 R193 R194 R209 R210 R225 R423 R424 R433 R434 R443 R444 R453 R454 R463 R464 R473 R474 R483 R484 R493 R494 R501: library part CMP-0023361-3, "RES, 100, 0.1%, 0.1 W, AEC-Q200 Grade 0, 0603", Manufacturer=Panasonic, Power_W=100mW, Supplier Part Number 1=P100DBCT-ND, TempCo="25 ppm/C", Tolerance_%=0.1%, Value2=0.1W, Value_Code=100R, ValueDisplayed=100
R141: library part CMP-0025700-4, "RES, 100, 5%, 0.1 W, AEC-Q200 Grade 0, 0603", Manufacturer=Vishay-Dale, Power_W=100mW, Supplier Part Number 1=541-100GCT-ND, TempCo="200 ppm/C", Tolerance_%=5%, Value2=0.1W, Value_Code=100R, ValueDisplayed=100
R143 R146: library part CMP-0025698-4, "RES, 100 k, 5%, 0.1 W, AEC-Q200 Grade 0, 0603", Manufacturer=Vishay-Dale, Power_W=100mW, Supplier Part Number 1=541-100KGCT-ND, TempCo="200 ppm/C", Tolerance_%=5%, Value2=0.1W, Value_Code=100k
R147: library part CMP-0025698-4, "RES, 100 k, 5%, 0.1 W, AEC-Q200 Grade 0, 0603", Manufacturer=Vishay-Dale, PartNumber=CRCW0603100KJNEA, Power_W=100mW, Supplier Part Number 1=541-100KGCT-ND, TempCo="200 ppm/C", Tolerance_%=5%, Value2=0.1W, Value_Code=100k
R189 R195: library part CMP-0026822-3, "RES, 0, 5%, 0.063 W, AEC-Q200 Grade 0, 0402", Manufacturer=Vishay-Dale, Power_W=63mW, Supplier Part Number 1=541-0.0JCT-ND, TempCo="200 ppm/C", Tolerance_%=5%, Value2=0.063W, Value_Code=0000, ValueDisplayed=0
R203 R205 R207 R211 R215 R217 R219 R222 R226 R230 R232 R234 R236 R238 R240 R242: library part CMP-0015428-3, "RES, 100, 1%, 1 W, AEC-Q200 Grade 0, 2512", Manufacturer=Vishay-Dale, Power_W=1W, Supplier Part Number 1=541-100AFCT-ND, TempCo="100 ppm/C", Tolerance_%=1%, Value_Code=100R, ValueDisplayed=100
RT1 RT2 RT3 RT4 RT5 RT6 RT7 RT8 RT9 RT10 RT11 RT12 RT13 RT14 RT15 RT16 RT17 RT18 RT19 RT20 RT21 RT22 RT23 RT24 RT25 RT26 RT27 RT28 RT29 RT30 RT31 RT32: library part CMP-0002359-3, "Thermistor NTC, 10k ohm, 2%, 0603", Manufacturer=Panasonic, Power_W=100mW, Supplier Part Number 1=P12012CT-ND, Tolerance_%=2%
T1 T2: library part CMP-0086619-1, "BMS TRANSFORMER", Manufacturer=Pulse
TP1: library part CMP-0055147-1, "Test Point, Multipurpose, Red, TH", Color=Red, Manufacturer=Keystone, PartNumber=5010, Supplier Part Number 1=36-5010-ND
TP2: library part CMP-0055148-1, "Test Point, Multipurpose, Black, TH", Color=Black, Manufacturer=Keystone, PartNumber=5011, Supplier Part Number 1=36-5011-ND
U1 U2 U9 U15: library part CMP-0093261-1, "24-V, 2-Channel ESD Protection Diode for In-Vehicle Networks", Breakdown Voltage=25.5V, Clamping Voltage=32V, Manufacturer="Texas Instruments", Operating Temperature Range="-55°C to +150°C", PartNumber=ESD652, ValueDisplayed=3pF
U3 U18: library part CMP-04910-000007-1, "IC PWR SWITCH N-CHAN 1:1 SOT23-6", Ambient Temperature Range High=+105°C, Ambient Temperature Range Low=-40°C, Manufacturer="Texas Instruments", Max Junction Temp=+150°C, Max Supply Voltage=18V, Min Supply Voltage=2.7V, Nominal Supply Current=49-62uA, Package=DBV0006A, Temperature="-40°C to +105°C"
U4 U19: library part CMP-0750035-3, "SafeTI™ Precision Monitor With Integrated Hardware Protector for Lithium-Ion, Lithium Phosphate, Lithium Titanate Battery Pack, PAP0064F (HTQFP-64)", Alternate Manufacturer="Texas Instruments"
U5 U20: library part CMP-0086166-2, "Low-capacitance, 2:1 (SPDT) 4-channel, powered-off protection switch with 1.8 V logic, PW0016A (TSSOP-16)", Alternate Manufacturer="Texas Instruments", Operating Temperature Range="-40 to 125 C", Rating=Catalog
U7 U8 U22 U23: library part CMP-0090991-1, "5-V, 8: 1, 1-channel general-purpose multiplexer with 1.8-V logic control 16-TSSOP -40 to 125", Digikey Part Number=296-TMUX1308PWRCT-ND, Manufacturer="Texas Instruments", Max Supply Voltage=5.5V, Min Supply Voltage=1.62V, Mouser Part Number=595-TMUX1308PWR, Nominal Supply Current=1uA, On State Resistance=75-650Ω, Operating Temperature Range="-40°C to +125°C"
U16: library part CMP-0094645-1, "Analog Switch ICs 3-pA on-state leakage current, 5-V, 1:1 (SPST), 1-channel precision switch (active high) 5-SC70 -40 to 125", Digikey Part Number=296-TMUX1102DCKRCT-ND, Manufacturer="Texas Instruments", Max Supply Voltage=5.5V, Min Supply Voltage=1.08V, Mouser Part Number=595-TMUX1102DCKR, Nominal Supply Current=0.003uA, On State Resistance=1.8Ω, Operating Temperature Range="-40°C to +125°C"
U17: library part CMP-0078444-2, "High-Speed, Low-Power, Robust EMC Quad-Channel Digital Isolator, DW0016B (SOIC-16)", Alternate Manufacturer="Texas Instruments", Alternate PartNumber=ISO7742DW, Operating Temperature Range="-55 to 125 C", Rating=Catalog

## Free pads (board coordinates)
  round 0 hole 133.86 unplated paste+0 mask+0: 0(190,160) 0(6620,205) 0(6720,2415) ""(405,2905)
  rect 0x0 hole 20 square unplated mask+1.97: ""(6833.94,421.12) ""(6833.94,541.49) ""(6833.94,661.87) ""(6833.94,782.24) ""(6833.94,902.61) ""(6833.94,1022.99) ""(6833.94,1143.36) ""(6833.94,1263.73) ""(6833.94,1384.11) ""(6833.94,1504.48) ""(6833.94,1624.85) ""(6833.94,1745.23) ""(6833.94,1865.6) ""(6833.94,1985.97) ""(6833.94,2106.35) ""(6833.94,2226.72) ""(6833.94,2347.09) ""(6833.94,2467.47) ""(6833.94,2587.84) ""(6835,60) ""(6835,180.37) ""(6835,300.75) ""(6835,2730) ""(6835,2848.46) ""(6835,2966.92) ""(6835,3085.38) ""(6835,3203.85) ""(6835,3322.31) ""(6835,3440.77) ""(6835,3559.23) ""(6835,3677.69) ""(6835,3796.15) ""(6835,3914.61) ""(6880,1300) ""(6885,2625) ""(6940,1300) ""(6946.82,2625) ""(7000,1300) ""(7008.64,2625) ""(7070.45,2625) ""(7075,1300) ""(7132.27,2625) ""(7135,1300) ""(7194.09,2625) ""(7195,1300) ""(7238.94,413.23) ""(7238.94,531.69) ""(7238.94,650.15) ""(7238.94,768.61) ""(7238.94,887.07) ""(7238.94,1005.54) ""(7238.94,1124) ""(7238.94,1242.46) ""(7238.94,1363.23) ""(7238.94,1481.69) ""(7238.94,1600.15) ""(7238.94,1718.61) ""(7238.94,1837.07) ""(7238.94,1955.54) ""(7238.94,2074) ""(7238.94,2192.46) ""(7238.94,2310.92) ""(7238.94,2429.38) ""(7238.94,2547.84) ""(7240,70) ""(7240,178.46) ""(7240,296.92) ""(7255.91,2625) ""(7317.73,2625) ""(7379.54,2625) ""(7441.36,2625) ""(7503.18,2625) ""(7565,2625)

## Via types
v1: diameter 20, hole 10, Top Layer to Bottom Layer, tented both sides, 1385 vias
v2: diameter 22.01, hole 12.01, Top Layer to Bottom Layer, tented both sides, 405 vias
v3: diameter 19.68, hole 7.87, Top Layer to Bottom Layer, 72 vias

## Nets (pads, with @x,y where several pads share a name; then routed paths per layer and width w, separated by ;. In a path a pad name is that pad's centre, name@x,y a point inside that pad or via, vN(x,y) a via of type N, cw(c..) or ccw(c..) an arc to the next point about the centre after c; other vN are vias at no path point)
A0_CVDD: C1.2 J8.2 J20.1 Q37.2 R140.1 U16.5 | length 579.5
  Top Layer w8: R140.1@7389.24,3047.47 7389.24,3046.49 7411.65,3024.08 ; Q37.2@7412.65,2993.37 7412.65,3022.08
  Top Layer w10: Q37.2@7412.65,2993.37 7412.65,2902.63 7423.82,2891.46 U16.5@7423.82,2881.61 7406.06,2881.61 7336.88,2881.61 J8.2@7297.24,2841.97 7297.24,2760.97 J20.1@7346.24,2711.97 7351.24,2706.97 C1.2@7452.61,2706.97
A0_GND: C1.1 C2.2 C120.1 J20.5 Q38.3 R196.1 U16.3 U17.9 U17.15 | length 663.5
  Top Layer w8: C120.1@6900.24,3293.35 6900.24,3133.22 6910.24,3123.22 U17.9@6947.13,3123.22 ; U17.9@6954.95,3123.57 6955.59,3122.93 6955.59,3072.61 v2(6956.24,3071.97) ; v2(7211.24,3036.97) 7215.03,3036.97 7228.03,3049.97 C2.2@7257.61,3049.97 7254.95,3052.64 U17.15@7254.95,3123.57 ; v2(7371.53,3155) 7373.06,3155 7398.93,3180.87 7428.13,3180.87 7435.95,3188.68 Q38.3@7435.95,3204.39 ; U16.3@7475,2795 7475,2788.87 7478.87,2785 7478.87,2781.28 7495,2765.16 7495,2707.89 7495.92,2706.97 C1.1@7499.86,2706.97
  Top Layer w10: U16.3@7475,2795 7475,2804.84 7485.16,2815 R196.1@7540,2815
A0_NFAULT: J8.8 J20.4 | length 150.3
  Top Layer w10: J8.8@6997.24,2841.97 6997.24,2760.97 J20.4@7046.24,2711.97
A0_RX: J8.4 J20.2 | length 150.3
  Top Layer w10: J8.4@7197.24,2841.97 7197.24,2760.97 J20.2@7246.24,2711.97
A0_TX: J8.6 J20.3 U16.2 | length 614.8
  Top Layer w8: U16.2@7449.41,2811.73 U16.2@7449.41,2795 7449.48,2794.93 7449.48,2755.52 v2(7449.56,2755.44)
  Top Layer w10: J8.6@7097.24,2841.97 7097.24,2760.97 J20.3@7146.24,2711.97
  Bottom Layer w8: J8.6@7097.24,2841.97 7108.5,2830.71 7108.5,2796.5 7115.38,2789.62 7360.38,2789.62 7394.56,2755.44 v2(7449.56,2755.44)
A1_AVDD: C168.2 R157.2 U19.38 | length 199.9
  Top Layer w8: U19.38@4926.18,2666.38 4994.62,2666.38 4996.63,2668.39 C168.2@5063.74,2668.39
  Top Layer w10: C168.2@5066.38,2655 5066.38,2613.7 5080.08,2600 R157.2@5080.87,2600
A1_BAT: C162.2 C163.1 D3.1 R156.2 R179.1 R188.1 U19.1 | length 875.8
  Top Layer w10: U19.1@4468.27,2863.23 U19.1@4477.36,2863.23
  Top Layer w20: R156.2@4030,2955 4030,2960 4045,2975 4177.36,2975 4197.36,2955 4377.7,2955 4382.48,2959.78 v2(4383.02,2959.78) 4383.41,2959.4 4424.96,2959.4 C163.1@4429.36,2955 4432.36,2952 4432.36,2910 4457.83,2884.53 U19.1@4457.83,2867.32
  Bottom Layer w10: C162.2@4337.3,2981.5 4337.3,2980.51 4380.22,2937.59 v2(4382.53,2937.59) ; v2@4383.02,2934.78 4385.83,2937.59 4459.77,2937.59 D3.1@4482.36,2915
  Bottom Layer w20: R188.1@4166.77,2981.5 C162.2@4337.3,2981.5
A1_BBN: R183.1 U19.63 | length 679.5
  Top Layer w8: 4040.35,3073 4063.16,3050.19 4256.01,3050.19 4287.2,3019 4483.94,3019 4497.75,3005.19 4567.53,3005.19 4572.21,3000.5 U19.63@4572.21,2956.58
  Top Layer w10: R183.1@4001.5,3130 4002.48,3130 4033,3099.48 4033,3080.35 4040.35,3073
A1_BBN_CELL: J16.1 R182.1 | length 101.8
  Top Layer w8: J16.1@3637.36,3140 3709.88,3140 3729.88,3120 R182.1@3730.87,3120
A1_BBP: R174.1 U19.64 | length 629.4
  Top Layer w8: R174.1@3999.84,3055 4007.48,3055 4012.18,3050.3 4012.18,3049.69 4025.68,3036.19 4236.17,3036.19 4267.36,3005 4478.14,3005 4491.95,2991.19 4549.31,2991.19 4554,2986.5 4554,2940.13 U19.64@4554.13,2940
A1_BBP_CELL: J16.2 R173.1 | length 135.1
  Top Layer w8: J16.2@3610.27,3030 J16.2@3635.27,3055 ; J16.2@3637.36,3040 3714.88,3040 3729.88,3055 R173.1@3730.87,3055
A1_CB0: C218.2 C223.1 R497.1 R499.2 R500.2 U19.34 | length 1823
  Top Layer w10: U19.34@4926.18,2587.64 4927.09,2586.73 4957.25,2586.73 4982.06,2561.92 4982.06,2547.87 v2(4984.36,2545.57)
  Bottom Layer w10: R497.1@6383.74,1915 v1@6383.74,2016.38
  Bottom Layer w15: R497.1@6386.54,1922.76 R497.1@6390.47,1922.76
  Bottom Layer w20: v2(4984.36,2545.57) 4984.36,2453.01 5002.36,2435 5017.36,2435 5078.86,2435 C223.1@5082.36,2438.5 5082.36,2370 5110.36,2342 5770.36,2342 5883.36,2229 6293.36,2229 6302.36,2220 6302.36,2153.3 ; 6302.36,2118.3 6314.41,2106.25
  other v1: 6322.36,2020 6387.36,2020 6452.36,2020 6517.36,2020 6582.36,2020 6647.36,2020 6322.36,2060 6387.36,2060 6452.36,2060 6517.36,2060 6582.36,2060 6647.36,2060 6322.36,2115 6387.36,2115 6452.36,2115 6517.36,2115 6582.36,2115 6647.36,2115 6322.36,2155 6387.36,2155 6452.36,2155 6517.36,2155 6582.36,2155 6647.36,2155
A1_CB1: C214.2 C218.1 R487.1 R489.2 R492.2 U19.32 | length 2510.3
  Top Layer w8: U19.32@4849.41,2491.18 4849.41,2467.56 4866.15,2450.82 4879.11,2450.82 v2(4919.36,2410.57)
  Bottom Layer w10: 6392.36,1335 6395.12,1332.24 R487.1@6395.12,1290
  Bottom Layer w20: v2(4919.36,2410.57) 4919.74,2410.19 4919.74,2397.54 4952.28,2365 C214.2@4953.27,2365 ; C218.1@5017.36,2368.5 5015.61,2366.75 4955.02,2366.75 C214.2@4953.27,2365 ; v1(6292.72,1385) 6277.36,1385 6257.36,1405 6257.36,2180 6234.36,2203 5844.36,2203 5731.36,2316 4964.98,2316 4953.27,2327.72 C214.2@4953.27,2365
  other v1: 6387.36,1375 6452.36,1375 6517.36,1375 6582.36,1375 6647.36,1375 6387.36,1415 6452.36,1415 6517.36,1415 6582.36,1415 6647.36,1415 6387.36,1470 6452.36,1470 6517.36,1470 6582.36,1470 6647.36,1470 6387.36,1510 6452.36,1510 6517.36,1510 6582.36,1510 6647.36,1510
A1_CB2: C210.2 C214.1 R477.1 R479.2 R482.2 U19.30 | length 1305.1
  Top Layer w8: U19.30@4810.04,2491.18 4810.04,2452.32 v2(4852.36,2410)
  Bottom Layer w10: R477.1@5877.36,2010 5877.36,2055
  Bottom Layer w20: v2(4852.36,2410) 4852.75,2409.62 4852.75,2401.54 4889.29,2365 C214.1@4890.28,2365 4890.28,2311.02 4879.25,2300 C210.2@4878.27,2300 ; C210.2@4887.95,2296.88 4887.95,2291.3 4893.53,2291.3 4894.83,2290 5682.36,2290 5752.36,2220 v1(5752.36,2090)
  other v1: 5812.36,2085 5877.36,2085 5942.36,2085 6007.36,2085 6072.36,2085 6137.36,2085 5812.36,2125 5877.36,2125 5942.36,2125 6007.36,2125 6072.36,2125 6137.36,2125
A1_CB3: C206.2 C210.1 R467.1 R469.2 R472.2 U19.28 | length 1745.8
  Top Layer w8: U19.28@4770.67,2491.18 4770.67,2446.49 4778.37,2438.79 4778.37,2427.78 4792.36,2413.79 v2(4792.36,2410)
  Bottom Layer w10: R467.1@5896.38,1610 5896.38,1648.62
  Bottom Layer w20: v2(4792.36,2410) 4792.75,2409.62 4792.75,2387.02 C206.2@4805.08,2374.69 ; C206.2@4814.76,2365 4815.02,2364.74 4815.02,2300.26 C210.1@4815.28,2300 4816.26,2300 4852.26,2264 5671.59,2264 5719.36,2216.23 5719.36,1653 v1(5725.86,1646.5)
  other v1: 5822.36,1675 5887.36,1675 5952.36,1675 6017.36,1675 6082.36,1675 6147.36,1675 5822.36,1715 5887.36,1715 5952.36,1715 6017.36,1715 6082.36,1715 6147.36,1715
A1_CB4: C202.2 C206.1 R457.1 R459.2 R462.2 U19.26 | length 2281.1
  Top Layer w8: U19.26@4731.3,2491.18 4731.3,2419.85 4737.36,2413.79 v2(4737.36,2410)
  Bottom Layer w10: R457.1@5893.74,1190 5893.74,1248.62
  Bottom Layer w20: v2(4737.36,2410) 4737.75,2409.62 4737.75,2379.03 4742.09,2374.69 4742.09,2373.7 4750.79,2365 C206.1@4751.77,2365 4747.52,2360.75 4747.52,2304.25 C202.2@4743.27,2300 4743.27,2251.3 4756.57,2238 5644.36,2238 5677.11,2205.25 5672.36,2200.5 5672.36,1777.55 5693.36,1756.55 5693.36,1524.86 5712.86,1505.36 5712.86,1234.5 v1(5732.36,1215)
  other v1: 5822.36,1260 5887.36,1260 5952.36,1260 6017.36,1260 6082.36,1260 6147.36,1260 5822.36,1300 5887.36,1300 5952.36,1300 6017.36,1300 6082.36,1300 6147.36,1300
A1_CB5: C201.2 C202.1 R447.1 R451.2 R452.2 U19.24 | length 909.9
  Top Layer w8: v2(4690.36,2410) 4691.15,2410.78 4691.15,2490.4 U19.24@4691.93,2491.18
  Bottom Layer w10: R447.1@5318.74,1988.15 5318.74,2031.38
  Bottom Layer w20: v2(4690.36,2410) 4689.98,2409.62 4689.98,2376.71 4687.95,2374.69 4687.95,2373.7 4679.25,2365 C201.2@4678.27,2365 4679.27,2364 4679.27,2301 C202.1@4680.28,2300 4680.28,2251.3 4719.57,2212 5152.19,2212 5202.36,2161.82 v1(5202.36,2101.25)
  other v1: 5272.36,2075 5337.36,2075 5402.36,2075 5467.36,2075 5532.36,2075 5597.36,2075 5272.36,2115 5337.36,2115 5402.36,2115 5467.36,2115 5532.36,2115 5597.36,2115
A1_CB6: C195.2 C201.1 R438.1 R441.2 R442.2 U19.22 | length 1413.9
  Top Layer w8: v2(4627.36,2410) 4652.56,2435.2 U19.22@4652.56,2491.18
  Bottom Layer w10: R438.1@5318.74,1598.77 5318.74,1651.38
  Bottom Layer w20: v2(4627.36,2410) 4626.98,2409.62 4626.98,2376.7 4624.96,2374.69 4624.96,2373.7 4616.26,2365 C201.1@4615.28,2365 4614.27,2364 4614.27,2301 C195.2@4613.27,2300 4613.27,2292.38 4614.35,2291.3 4614.35,2251.3 4679.65,2186 5141.42,2186 5172.36,2155.05 5172.36,1670 v1(5187.36,1655)
  other v1: 5272.36,1670 5337.36,1670 5402.36,1670 5467.36,1670 5532.36,1670 5597.36,1670 5272.36,1710 5337.36,1710 5402.36,1710 5467.36,1710 5532.36,1710 5597.36,1710
A1_CB7: C190.2 C195.1 R427.1 R430.2 R431.2 U19.20 | length 1908
  Top Layer w8: v2(4557.36,2410) 4560.04,2412.68 4570.04,2412.68 4611.28,2453.92 4611.28,2489.28 U19.20@4613.19,2491.18
  Bottom Layer w10: R427.1@5318.74,1173.77 5318.74,1221.38 5322.36,1225
  Bottom Layer w20: C190.2@4548.27,2365 4549.27,2364 4549.27,2301 C195.1@4550.28,2300 4550.28,2234.02 4624.29,2160 5130.65,2160 5142.36,2148.28 5142.36,1275 v1(5187.36,1230) ; C190.2@4548.27,2365 4556.98,2373.7 4556.98,2409.62 v2(4557.36,2410)
  other v1: 5267.36,1260 5332.36,1260 5397.36,1260 5462.36,1260 5527.36,1260 5592.36,1260 5267.36,1300 5332.36,1300 5397.36,1300 5462.36,1300 5527.36,1300 5592.36,1300
A1_CB8: C190.1 C220.2 R419.2 R421.2 R498.1 U19.18 | length 548.1
  Top Layer w8: v2@4482.36,2415 4482.79,2414.58 4486.94,2414.58 4521.47,2449.1 4560.49,2449.1 4571.91,2460.53 4571.91,2489.28 U19.18@4573.82,2491.18
  Bottom Layer w10: R498.1@4768.74,1995 4768.74,2046.38 4772.36,2050
  Bottom Layer w20: v2(4482.36,2410) 4482.36,2409.46 4485.28,2406.54 C190.1@4485.28,2365 4481.77,2361.5 4481.77,2303.5 C220.2@4478.27,2300 4478.27,2257.17 4606.51,2128.92 v1@4606.51,2115.85
  other v1: 4702.36,2070 4767.36,2070 4832.36,2070 4897.36,2070 4962.36,2070 5027.36,2070 4607.36,2110 4702.36,2110 4767.36,2110 4832.36,2110 4897.36,2110 4962.36,2110 5027.36,2110
A1_CB9: C216.2 C220.1 R488.1 R490.2 R491.2 U19.16 | length 1271.8
  Top Layer w8: v2(4387.36,2510) 4390.04,2512.68 4398.47,2512.68 4453.74,2567.95 U19.16@4477.36,2567.95
  Bottom Layer w10: R488.1@4768.74,1610 4768.74,1651.38
  Bottom Layer w20: C216.2@4271.77,2450 4357.36,2450 4372.17,2464.81 ; v2(4387.36,2510) 4386.98,2509.62 4386.98,2479.62 4372.17,2464.81 ; v1(4607.36,1640) 4607.36,1815 4567.36,1855 4567.36,2131.3 4488.67,2210 4426.99,2210 4415.28,2221.72 C220.1@4415.28,2300 4415.28,2421.7 4372.17,2464.81
  other v1: 4697.36,1665 4762.36,1665 4827.36,1665 4892.36,1665 4957.36,1665 5022.36,1665 4697.36,1705 4762.36,1705 4827.36,1705 4892.36,1705 4957.36,1705 5022.36,1705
